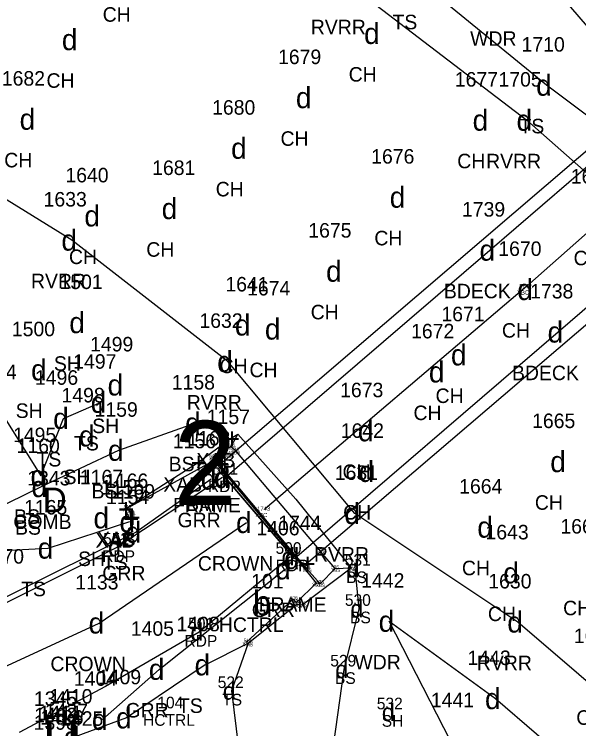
# Model space of a CAD drawing. Extents: x 461160 to 461373, y 202903 to 203086.
# Drawn here: x 461284.61 to 461314.15, y 202948.72 to 202986.14 of the extents above; entities that cross this region are included whole.
import ezdxf

# ---------------------------------------------------------------- set-up
doc = ezdxf.new("R2010")
doc.units = 0
for name, color, linetype in [('Level 1', 7, 'Continuous'), ('Level 11', 7, 'Continuous'), ('Level 12', 7, 'Continuous'), ('Level 14', 7, 'Continuous'), ('Level 15', 7, 'Continuous'), ('Level 17', 7, 'Continuous'), ('Level 34', 7, 'Continuous'), ('Level 35', 7, 'Continuous'), ('Level 37', 7, 'Continuous'), ('Level 46', 7, 'Continuous'), ('Level 47', 7, 'Continuous'), ('Level 48', 7, 'Continuous'), ('Level 49', 7, 'Continuous')]:
    doc.layers.add(name, color=color, linetype=linetype)

msp = doc.modelspace()

# ---------------------------------------------------------------- linework, layer by layer
at = {"layer": 'Level 11'}
for p, q in [((461295.507, 202961.871), (461289.972, 202958.214)), ((461289.972, 202958.214), (461281.455, 202953.963)), ((461299.052, 202957.724), (461294.279, 202953.778)), ((461294.279, 202953.778), (461289.379, 202950.925)), ((461289.379, 202950.925), (461284.854, 202948.511))]:
    msp.add_line(p, q, dxfattribs=at)
msp.add_lwpolyline([(461295.638, 202961.869), (461299.226, 202957.684)], dxfattribs=at)
at = {"layer": 'Level 12'}
msp.add_line((461346.056, 202948.738), (461294.056, 203009.532), dxfattribs=at)
for points in [[(461294.92, 202961.79), (461290.984, 202959.008), (461284.162, 202955.604), (461280.179, 202955.252)], [(461289.215, 202949.205), (461292.197, 202951.826), (461298.809, 202957.086)]]:
    msp.add_lwpolyline(points, dxfattribs=at)
at = {"layer": 'Level 14'}
msp.add_lwpolyline([(461316.688, 202932.462), (461313.104, 202939.736), (461307.447, 202948.079), (461304.23, 202954.345), (461309.796, 202950.292), (461316.233, 202944.748), (461322.68, 202941.312), (461327.281, 202938.198)], dxfattribs=at)
at = {"layer": 'Level 17'}
for points in [[(461271.342, 203006.356), (461278.053, 203003.256), (461286.412, 202998.583), (461294.243, 202992.971), (461302.269, 202987.612), (461311.447, 202980.59), (461317.239, 202975.481), (461319.309, 202973.643)], [(461329.105, 202940.329), (461320.674, 202945.977), (461310.964, 202954.304), (461302.434, 202959.989), (461295.777, 202967.953), (461287.62, 202974.31), (461283.863, 202976.623)]]:
    msp.add_lwpolyline(points, dxfattribs=at)
at = {"layer": 'Level 34'}
for points in [[(461326.916, 202981.421), (461313.074, 202969.494), (461299.278, 202957.624), (461295.638, 202961.869), (461309.508, 202973.783), (461323.296, 202985.661), (461326.916, 202981.421)], [(461324.72, 202983.644), (461311.442, 202971.896), (461297.739, 202960.242)]]:
    msp.add_lwpolyline(points, dxfattribs=at)
at = {"layer": 'Level 35'}
for p, q in [((461295.968, 202963.506), (461296.303, 202964.142)), ((461295.968, 202963.506), (461295.01, 202962.94)), ((461296.183, 202963.267), (461295.968, 202963.506)), ((461295.01, 202962.94), (461295.241, 202962.672)), ((461295.01, 202962.94), (461295.078, 202962.768)), ((461295.078, 202962.768), (461290.526, 202960.267)), ((461295.434, 202962.319), (461295.078, 202962.768)), ((461299.916, 202957.097), (461295.241, 202962.672)), ((461290.526, 202960.267), (461290.731, 202959.93)), ((461301.411, 202957.11), (461300.655, 202957.982)), ((461299.675, 202955.213), (461302.248, 202957.148)), ((461299.916, 202957.097), (461300.616, 202956.314)), ((461300.616, 202956.314), (461301.411, 202957.11)), ((461301.411, 202957.11), (461302.248, 202957.148)), ((461300.411, 202956.343), (461299.374, 202955.325)), ((461300.616, 202956.314), (461300.411, 202956.343)), ((461299.209, 202955.499), (461296.771, 202953.258)), ((461299.374, 202955.325), (461299.209, 202955.499)), ((461296.848, 202953.201), (461299.389, 202955.239)), ((461299.389, 202955.239), (461299.675, 202955.213))]:
    msp.add_line(p, q, dxfattribs=at)
for points in [[(461290.724, 202959.792), (461290.652, 202959.724), (461290.388, 202960.218), (461294.193, 202962.648), (461295.928, 202963.915), (461296.303, 202964.142)], [(461296.303, 202964.142), (461299.343, 202960.74), (461302.248, 202957.148)], [(461296.183, 202963.267), (461298.419, 202960.624), (461300.655, 202957.982)], [(461295.434, 202962.319), (461299.557, 202957.406), (461300.411, 202956.343)]]:
    msp.add_lwpolyline(points, dxfattribs=at)
at = {"layer": 'Level 37'}
for points in [[(461322.735, 202985.975), (461295.405, 202962.57)], [(461299.888, 202957.36), (461327.236, 202980.731)]]:
    msp.add_lwpolyline(points, dxfattribs=at)
at = {"layer": 'Level 48'}
for p, q in [((461302.659, 202955.002), (461302.452, 202957.107)), ((461301.869, 202951.826), (461302.659, 202955.002)), ((461301.078, 202946.096), (461301.869, 202951.826))]:
    msp.add_line(p, q, dxfattribs=at)
for points in [[(461321.29, 202974.86), (461317.717, 202978.484), (461312.473, 202982.423), (461305.824, 202987.874), (461301.65, 202990.994), (461300.034, 202993.51), (461304.787, 202998.277), (461312.691, 203003.124), (461318.698, 203006.786), (461322.707, 203009.684), (461325.345, 203012.481), (461324.782, 203012.846), (461322.016, 203009.952), (461316.942, 203006.65), (461311.004, 203002.871), (461303.318, 202997.851), (461297.451, 202992.823)], [(461321.29, 202974.86), (461317.717, 202978.484), (461312.473, 202982.423), (461305.824, 202987.874), (461301.65, 202990.994), (461300.034, 202993.51), (461304.787, 202998.277), (461312.691, 203003.124), (461318.698, 203006.786), (461322.707, 203009.684), (461325.345, 203012.481), (461324.782, 203012.846), (461322.016, 203009.952), (461316.942, 203006.65), (461311.004, 203002.871), (461303.318, 202997.851), (461297.451, 202992.823)], [(461262.397, 202991.157), (461268.172, 202986.514), (461275.177, 202981.097), (461279.904, 202974.246), (461281.802, 202966.659), (461283.93, 202965.263), (461286.001, 202961.968), (461287.188, 202964.973), (461289.154, 202965.814)], [(461262.397, 202991.157), (461268.172, 202986.514), (461275.177, 202981.097), (461279.904, 202974.246), (461281.802, 202966.659), (461283.93, 202965.263), (461286.001, 202961.968), (461287.188, 202964.973), (461289.154, 202965.814)], [(461294.096, 202964.725), (461290.058, 202963.299), (461286.054, 202961.4), (461281.542, 202959.198), (461277.133, 202957.003), (461280.61, 202956.648), (461283.332, 202958.017), (461286.382, 202958.177), (461290.659, 202959.565)], [(461294.096, 202964.725), (461290.058, 202963.299), (461286.054, 202961.4), (461281.542, 202959.198), (461277.133, 202957.003), (461280.61, 202956.648), (461283.332, 202958.017), (461286.382, 202958.177), (461290.659, 202959.565)], [(461211.555, 202934.121), (461222.234, 202936.16), (461232.093, 202938.078), (461241.693, 202939.978), (461251.734, 202942.643), (461261.209, 202945.054), (461270.211, 202947.385), (461280.824, 202950.466), (461289.045, 202954.252), (461296.764, 202959.518)], [(461294.593, 202952.063), (461296.848, 202953.201), (461295.974, 202950.697), (461296.588, 202945.726)], [(461294.593, 202952.063), (461290.48, 202949.284), (461287.747, 202948.275), (461286.711, 202947.403), (461288.313, 202945.529), (461294.278, 202942.049), (461301.603, 202936.541), (461306.215, 202932.756), (461310.378, 202928.695), (461312.884, 202930.112), (461314.866, 202931.237), (461309.977, 202933.052), (461306.465, 202937.375), (461306.039, 202938.806)]]:
    msp.add_lwpolyline(points, dxfattribs=at)

# ---------------------------------------------------------------- texts
at = {"layer": 'Level 1'}
for s, height, p in [('2', 4.4, (461292.951, 202960.441)), ('b', 1.3, (461297.09, 202954.654))]:
    msp.add_text(s, height=height, dxfattribs=at).set_placement(p)
at = {"layer": 'Level 14'}
msp.add_text('H', height=2, dxfattribs=at).set_placement((461286.096, 202947.152))
at = {"layer": 'Level 15'}
msp.add_text('D', height=1.3, dxfattribs=at).set_placement((461286.095, 202960.052))
at = {"layer": 'Level 46'}
for s, height, p in [(' CH  ', 0.76, (461288.952, 202985.75)), (' TS  ', 0.76, (461304.122, 202985.354)), (' RVRR  ', 0.76, (461299.846, 202985.092)), (' WDR  ', 0.76, (461308.19, 202984.488)), (' CH  ', 0.76, (461301.83, 202982.614)), (' CH  ', 0.76, (461286.009, 202982.289)), (' TS  ', 0.76, (461310.771, 202979.903)), (' CH  ', 0.76, (461298.261, 202979.25)), (' CH  ', 0.76, (461283.797, 202978.122)), (' CH  ', 0.76, (461307.513, 202978.073)), (' RVRR  ', 0.76, (461309.024, 202978.07)), (' CH  ', 0.76, (461294.868, 202976.601)), (' CH  ', 0.76, (461303.173, 202974.037)), (' CH  ', 0.76, (461291.235, 202973.441)), (' CH  ', 0.76, (461287.187, 202973.056)), (' CH  ', 0.76, (461313.604, 202972.992)), (' RVRR  ', 0.76, (461285.197, 202971.79)), (' BDECK  ', 0.76, (461306.813, 202971.263)), (' XBC  ', 0.22, (461310.847, 202971.456)), (' CH  ', 0.76, (461299.841, 202970.161)), (' CH  ', 0.76, (461309.852, 202969.202)), (' SH  ', 0.76, (461286.398, 202967.467)), (' CH  ', 0.76, (461295.069, 202967.341)), (' CH  ', 0.76, (461296.637, 202967.131)), (' BDECK  ', 0.76, (461310.379, 202966.974)), (' CH  ', 0.76, (461306.378, 202965.779)), (' RVRR  ', 0.76, (461293.354, 202965.433)), (' SH  ', 0.76, (461284.397, 202964.996)), (' CH  ', 0.76, (461305.222, 202964.884)), (' SH  ', 0.76, (461288.403, 202964.2)), (' TS  ', 0.76, (461287.452, 202963.294)), ('545', 0.17, (461295.768, 202963.506)), ('XBS', 0.17, (461295.754, 202963.336)), ('XBS', 0.17, (461295.969, 202963.097)), ('546', 0.17, (461295.977, 202963.267)), (' TS  ', 0.76, (461285.486, 202962.453)), (' BS  ', 0.76, (461292.406, 202962.205)), (' XAB  ', 0.76, (461293.858, 202962.395)), ('XBS', 0.17, (461294.796, 202962.77)), ('547', 0.17, (461294.81, 202962.94)), ('542', 0.17, (461294.878, 202962.768)), ('XBS', 0.17, (461295.653, 202962.919)), ('549', 0.17, (461295.665, 202963.089)), ('XAT', 0.17, (461294.858, 202962.598)), ('551', 0.609, (461294.961, 202962.023)), ('XBS', 0.17, (461295.027, 202962.502)), ('548', 0.17, (461295.041, 202962.672)), (' CH  ', 0.76, (461301.507, 202961.801)), (' SH  ', 0.76, (461286.903, 202961.529)), ('XAT', 0.17, (461295.214, 202962.149)), ('541', 0.17, (461295.282, 202962.319)), (' XAB  ', 0.76, (461292.123, 202961.128)), (' BS  ', 0.76, (461288.368, 202960.779)), ('RDP', 0.609, (461294.743, 202961.11)), (' FRAME  ', 0.76, (461292.632, 202960.05)), (' BM  ', 0.76, (461293.317, 202960.121)), (' CH  ', 0.76, (461311.577, 202960.186)), ('543', 0.17, (461290.326, 202960.267)), (' CH  ', 0.76, (461301.539, 202959.673)), (' COMB  ', 0.76, (461284.274, 202959.182)), (' BS  ', 0.76, (461284.311, 202959.448)), ('XAT', 0.17, (461290.306, 202960.097)), ('XAT', 0.17, (461290.511, 202959.76)), ('544', 0.17, (461290.531, 202959.93)), (' GRR  ', 0.76, (461292.868, 202959.27)), (' XBC  ', 0.22, (461297.144, 202959.802)), (' BS  ', 0.76, (461284.364, 202958.88)), (' XAB  ', 0.76, (461288.582, 202958.204)), (' XAB  ', 0.76, (461288.654, 202958.272)), ('552', 0.609, (461289.253, 202958.366)), ('500', 0.609, (461298.282, 202957.876)), ('RDP', 0.609, (461289.208, 202957.453)), (' RVRR  ', 0.76, (461300.011, 202957.469)), ('537', 0.17, (461300.455, 202957.982)), (' SH  ', 0.76, (461287.664, 202957.239)), (' TS  ', 0.76, (461288.957, 202957.045)), (' CROWN  ', 0.76, (461293.934, 202956.998)), ('XBS', 0.17, (461300.441, 202957.812)), ('531', 0.609, (461301.906, 202957.259)), ('RDP', 0.609, (461298.288, 202956.963)), ('XAT', 0.17, (461299.337, 202957.236)), ('513', 0.17, (461299.405, 202957.406)), ('536', 0.17, (461301.205, 202957.11)), ('521', 0.17, (461302.096, 202957.148)), (' CH  ', 0.76, (461307.758, 202956.756)), (' GRR  ', 0.76, (461288.932, 202956.488)), ('XBS', 0.17, (461299.702, 202956.927)), ('538', 0.17, (461299.716, 202957.097)), ('XBS', 0.17, (461301.197, 202956.94)), ('XAB', 0.17, (461302.03, 202956.978)), ('BS', 0.609, (461301.978, 202956.346)), (' TS  ', 0.76, (461284.68, 202955.657)), ('XAT', 0.17, (461300.191, 202956.173)), ('514', 0.17, (461300.259, 202956.343)), ('XBS', 0.17, (461300.402, 202956.144)), ('535', 0.17, (461300.416, 202956.314)), (' FRAME  ', 0.76, (461297.115, 202954.84)), ('XAT', 0.17, (461298.989, 202955.329)), ('516', 0.17, (461299.052, 202955.499)), ('515', 0.17, (461299.222, 202955.325)), ('519', 0.17, (461299.236, 202955.239)), ('530', 0.609, (461301.913, 202955.154)), (' CH  ', 0.76, (461313.056, 202954.66)), (' GRR  ', 0.76, (461296.757, 202954.566)), ('XAT', 0.17, (461299.154, 202955.155)), ('XAB', 0.17, (461299.171, 202955.069)), ('XAB', 0.17, (461299.457, 202955.043)), ('520', 0.17, (461299.467, 202955.213)), (' CH  ', 0.76, (461309.118, 202954.356)), ('BS', 0.609, (461302.185, 202954.241)), ('501', 0.609, (461293.709, 202953.93)), (' HCTRL  ', 0.76, (461295.033, 202953.784)), ('RDP', 0.609, (461293.515, 202953.017)), ('XAT', 0.17, (461296.551, 202953.088)), ('517', 0.17, (461296.619, 202953.258)), ('XAB', 0.17, (461296.63, 202953.031)), ('518', 0.17, (461296.696, 202953.201)), (' CROWN  ', 0.76, (461286.215, 202951.732)), ('529', 0.609, (461301.147, 202951.978)), (' WDR  ', 0.76, (461302.13, 202951.825)), (' RVRR  ', 0.76, (461308.541, 202951.784)), ('BS', 0.609, (461301.395, 202951.065)), ('522', 0.609, (461295.255, 202950.849)), ('TS', 0.609, (461295.49, 202949.936)), ('104', 0.609, (461292.094, 202949.784)), (' TS  ', 0.76, (461292.891, 202949.543)), ('532', 0.609, (461303.584, 202949.735)), (' GRR  ', 0.76, (461290.145, 202949.306)), ('HCTRL', 0.609, (461291.346, 202948.871)), ('SH', 0.609, (461303.843, 202948.822)), (' CH  ', 0.76, (461313.745, 202948.923))]:
    msp.add_text(s, height=height, dxfattribs=at).set_placement(p)
at = {"layer": 'Level 47'}
for s, height, p in [('d', 1.1, (461302.916, 202984.584)), ('d', 1.1, (461287.095, 202984.259)), ('d', 1.1, (461311.923, 202981.873)), ('d', 1.1, (461299.347, 202981.22)), ('d', 1.1, (461284.883, 202980.092)), ('d', 1.1, (461308.599, 202980.043)), ('d', 1.1, (461310.897, 202980.04)), ('d', 1.1, (461295.954, 202978.571)), ('d', 1.1, (461304.259, 202976.007)), ('d', 1.1, (461292.321, 202975.411)), ('d', 1.1, (461288.273, 202975.026)), ('d', 1.1, (461287.07, 202973.76)), ('d', 1.1, (461308.958, 202973.233)), ('d', 1.1, (461300.927, 202972.131)), ('d', 1.1, (461310.938, 202971.172)), ('+', 0.15, (461311.393, 202971.821)), ('d', 1.1, (461287.484, 202969.437)), ('d', 1.1, (461296.155, 202969.311)), ('d', 1.1, (461297.723, 202969.101)), ('d', 1.1, (461312.524, 202968.944)), ('d', 1.1, (461307.464, 202967.749)), ('d', 1.1, (461295.227, 202967.403)), ('d', 1.1, (461285.483, 202966.966)), ('d', 1.1, (461306.308, 202966.854)), ('d', 1.1, (461289.489, 202966.17)), ('d', 1.1, (461288.604, 202965.264)), ('d', 1.1, (461286.638, 202964.423)), ('d', 1.1, (461293.546, 202964.175)), ('d', 1.1, (461302.593, 202963.771)), ('d', 1.1, (461287.989, 202963.499)), ('+', 1.1, (461295.569, 202963.365)), ('d', 1.1, (461289.508, 202962.749)), ('+', 0.121, (461295.929, 202963.446)), ('+', 0.121, (461296.144, 202963.207)), ('d', 1.1, (461312.663, 202962.156)), ('+', 1.1, (461293.834, 202962.098)), ('+', 0.121, (461294.971, 202962.88)), ('+', 1.1, (461295.046, 202962.02)), ('d', 1.1, (461285.451, 202961.418)), ('+', 0.121, (461295.039, 202962.708)), ('+', 0.121, (461295.202, 202962.612)), ('d', 1.1, (461302.625, 202961.643)), ('d', 1.1, (461294.37, 202961.24)), ('d', 0.914, (461295.05, 202961.414)), ('d', 1.1, (461295.088, 202961.319)), ('+', 0.121, (461295.395, 202962.259)), ('d', 1.1, (461285.504, 202960.85)), ('d', 1.1, (461288.75, 202959.209)), ('+', 1.1, (461290.029, 202959.668)), ('+', 0.121, (461290.487, 202960.207)), ('+', 0.15, (461297.69, 202960.167)), ('d', 1.1, (461301.884, 202959.439)), ('d', 1.1, (461290.109, 202959.015)), ('+', 1.1, (461290.293, 202959.174)), ('+', 1.1, (461290.365, 202959.242)), ('+', 0.121, (461290.692, 202959.87)), ('d', 1.1, (461296.214, 202958.968)), ('d', 1.1, (461290.434, 202958.458)), ('d', 1.1, (461308.844, 202958.726)), ('d', 1.1, (461285.832, 202957.627)), ('d', 0.914, (461289.515, 202957.757)), ('d', 0.914, (461298.595, 202957.267)), ('d', 1.1, (461298.728, 202957.074)), ('d', 1.1, (461298.259, 202956.536)), ('+', 1.1, (461299.529, 202956.81)), ('+', 0.121, (461300.616, 202957.922)), ('+', 0.121, (461299.518, 202957.346)), ('d', 0.914, (461301.995, 202956.65)), ('d', 1.1, (461310.204, 202956.326)), ('+', 0.121, (461299.877, 202957.037)), ('+', 0.121, (461301.372, 202957.05)), ('+', 0.121, (461302.209, 202957.088)), ('+', 0.121, (461300.372, 202956.283)), ('+', 0.121, (461300.577, 202956.254)), ('+', 0.121, (461299.17, 202955.439)), ('d', 0.914, (461302.202, 202954.545)), ('+', 0.121, (461299.335, 202955.265)), ('+', 0.121, (461299.35, 202955.179)), ('+', 0.121, (461299.636, 202955.153)), ('d', 1.1, (461288.495, 202953.702)), ('d', 1.1, (461303.68, 202953.795)), ('d', 1.1, (461310.414, 202953.754)), ('d', 0.914, (461293.822, 202953.321)), ('+', 0.121, (461296.732, 202953.198)), ('+', 0.121, (461296.809, 202953.141)), ('d', 1.1, (461291.647, 202951.276)), ('d', 1.1, (461294.043, 202951.513)), ('d', 0.914, (461301.412, 202951.369)), ('d', 0.914, (461295.517, 202950.24)), ('d', 1.1, (461309.246, 202949.742)), ('d', 1.1, (461288.665, 202948.655)), ('d', 1.1, (461289.93, 202948.734)), ('d', 0.914, (461303.846, 202949.126)), ('d', 1.1, (461287.197, 202947.725))]:
    msp.add_text(s, height=height, dxfattribs=at).set_placement(p)
at = {"layer": 'Level 49'}
for s, height, p in [(' 1710 ', 0.76, (461310.882, 202984.183)), (' 1679 ', 0.76, (461298.132, 202983.53)), (' 1682 ', 0.76, (461283.671, 202982.402)), (' 1677 ', 0.76, (461307.387, 202982.353)), (' 1705 ', 0.76, (461309.673, 202982.35)), (' 1680 ', 0.76, (461294.679, 202980.881)), (' 1676 ', 0.76, (461303.008, 202978.317)), (' 1681 ', 0.76, (461291.54, 202977.721)), (' 1640 ', 0.76, (461286.998, 202977.336)), (' 1669 ', 0.76, (461313.457, 202977.272)), (' 1633 ', 0.76, (461285.858, 202976.07)), (' 1739 ', 0.76, (461307.761, 202975.543)), (' 1675 ', 0.76, (461299.715, 202974.441)), (' 1670 ', 0.76, (461309.663, 202973.482)), (' 1501 ', 0.76, (461286.691, 202971.747)), (' 1641 ', 0.76, (461295.374, 202971.621)), (' 1674 ', 0.76, (461296.511, 202971.411)), (' 1742 ', 0.22, (461310.938, 202971.786)), (' 1738 ', 0.76, (461311.33, 202971.254)), (' 1671 ', 0.76, (461306.683, 202970.059)), (' 1632 ', 0.76, (461294.015, 202969.713)), (' 1500 ', 0.76, (461284.196, 202969.276)), (' 1672 ', 0.76, (461305.096, 202969.164)), (' 1499 ', 0.76, (461288.292, 202968.48)), (' 1497 ', 0.76, (461287.41, 202967.574)), (' 1494 ', 0.76, (461282.186, 202967.023)), (' 1496 ', 0.76, (461285.405, 202966.733)), (' 1158 ', 0.76, (461292.568, 202966.485)), (' 1673 ', 0.76, (461301.381, 202966.081)), (' 1498 ', 0.76, (461286.795, 202965.809)), (' 1159 ', 0.76, (461288.527, 202965.059)), (' 1157 ', 0.76, (461294.4, 202964.675)), (' 1665 ', 0.76, (461311.433, 202964.466)), (' 1495 ', 0.76, (461284.257, 202963.728)), (' 1642 ', 0.76, (461301.413, 202963.953)), (' 1156 ', 0.76, (461292.626, 202963.408)), (' 1168 ', 0.76, (461293.374, 202963.55)), (' 1160 ', 0.76, (461284.445, 202963.16)), (' 1631 ', 0.76, (461301.103, 202961.749)), (' 1343 ', 0.76, (461285.001, 202961.462)), (' 1167 ', 0.76, (461287.754, 202961.519)), (' 1166 ', 0.76, (461289.074, 202961.325)), (' 1664 ', 0.76, (461307.614, 202961.036)), (' 1155 ', 0.76, (461288.86, 202960.978)), (' 1169 ', 0.76, (461289.435, 202960.768)), (' 1154 ', 0.76, (461289.124, 202960.484)), (' 1165 ', 0.76, (461284.836, 202959.937)), (' 1743 ', 0.22, (461297.235, 202960.132)), (' 1406 ', 0.76, (461296.996, 202958.846)), (' 1744 ', 0.76, (461298.144, 202959.12)), (' 1663 ', 0.76, (461312.912, 202958.94)), (' 1643 ', 0.76, (461308.992, 202958.636)), (' 1170 ', 0.76, (461282.571, 202957.364)), (' 1133 ', 0.76, (461287.517, 202956.012)), (' 101 ', 0.76, (461296.726, 202956.064)), (' 1442 ', 0.76, (461302.486, 202956.105)), (' 1630 ', 0.76, (461309.139, 202956.064)), (' 1405 ', 0.76, (461290.423, 202953.586)), (' 1408 ', 0.76, (461292.819, 202953.823)), (' 1644 ', 0.76, (461313.619, 202953.203)), (' 1443 ', 0.76, (461308.052, 202952.052)), (' 1404 ', 0.76, (461287.441, 202950.965)), (' 1409 ', 0.76, (461288.703, 202951.044)), (' 1345 ', 0.76, (461285.352, 202949.912)), (' 1410 ', 0.76, (461286.156, 202950.035)), (' 1441 ', 0.76, (461306.134, 202949.839)), (' 1403 ', 0.76, (461285.366, 202949.054)), (' 1411 ', 0.76, (461285.613, 202949.163)), (' 1427 ', 0.76, (461285.92, 202949.264)), (' 1398 ', 0.76, (461285.336, 202948.663)), (' 1426 ', 0.76, (461285.686, 202948.934)), (' 1425 ', 0.76, (461286.723, 202948.87))]:
    msp.add_text(s, height=height, dxfattribs=at).set_placement(p)

doc.saveas('drawing.dxf')
